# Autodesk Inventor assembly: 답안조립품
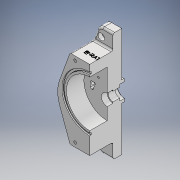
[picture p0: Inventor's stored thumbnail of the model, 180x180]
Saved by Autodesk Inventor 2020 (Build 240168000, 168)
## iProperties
Created: 2023-11
Part Number: 답안조립품
Document SubType Name: Weldment
Designer: CAD14
Weld Material: Welded Aluminum-6061
Author: CAD14
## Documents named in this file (2)
- C:\Users\CAD14\Desktop\731106V1010\답안조립품.iam
- C:\Users\CAD14\Desktop\731106V1010\본체.ipt
